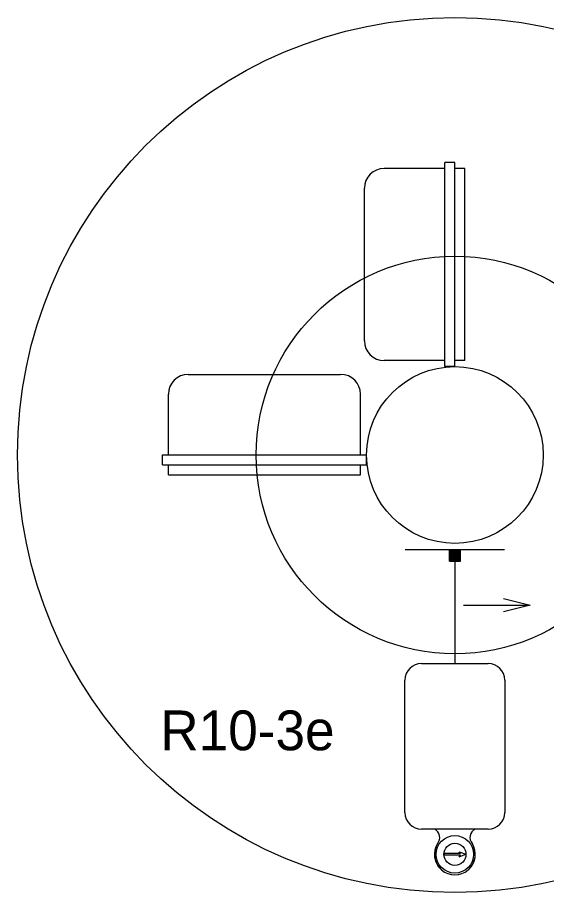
# Model space of a CAD drawing. Extents: x 1370050 to 1370716, y 380076 to 380502.
# Drawn here: x 1370528.6 to 1370568.5, y 380268.8 to 380334.9 of the extents above; entities that cross this region are included whole.
import ezdxf

# ---------------------------------------------------------------- set-up
doc = ezdxf.new("R2010")
doc.units = 0
doc.layers.add('T_Drafting', color=7, linetype='Continuous')

msp = doc.modelspace()

# ---------------------------------------------------------------- linework, layer by layer
at = {"layer": 'T_Drafting'}
for p, q in [((1370560.87, 380323.464), (1370556.287, 380323.464)), ((1370560.87, 380308.505), (1370560.87, 380323.922)), ((1370561.62, 380323.922), (1370560.87, 380323.922)), ((1370561.62, 380308.505), (1370561.62, 380323.922)), ((1370562.37, 380323.464), (1370561.62, 380323.464)), ((1370562.37, 380308.964), (1370562.37, 380323.464)), ((1370554.787, 380310.464), (1370554.787, 380321.964)), ((1370560.87, 380308.964), (1370556.287, 380308.964)), ((1370562.37, 380308.964), (1370561.62, 380308.964)), ((1370561.62, 380308.505), (1370560.87, 380308.505)), ((1370541.495, 380307.922), (1370552.995, 380307.922)), ((1370539.995, 380301.839), (1370539.995, 380306.422)), ((1370554.495, 380301.839), (1370554.495, 380306.422)), ((1370539.537, 380301.839), (1370554.953, 380301.839)), ((1370539.537, 380301.089), (1370539.537, 380301.839)), ((1370554.953, 380301.089), (1370554.953, 380301.839)), ((1370539.537, 380301.089), (1370554.953, 380301.089)), ((1370539.995, 380300.339), (1370539.995, 380301.089)), ((1370554.495, 380300.339), (1370554.495, 380301.089)), ((1370539.995, 380300.339), (1370554.495, 380300.339)), ((1370565.37, 380294.672), (1370557.87, 380294.672)), ((1370561.203, 380293.839), (1370561.203, 380294.672)), ((1370561.203, 380293.845), (1370562.031, 380294.672)), ((1370561.203, 380293.859), (1370562.017, 380294.672)), ((1370561.203, 380293.873), (1370562.002, 380294.672)), ((1370561.203, 380293.887), (1370561.988, 380294.672)), ((1370561.203, 380293.901), (1370561.974, 380294.672)), ((1370561.203, 380293.915), (1370561.96, 380294.672)), ((1370561.203, 380293.93), (1370561.946, 380294.672)), ((1370561.203, 380293.944), (1370561.932, 380294.672)), ((1370561.203, 380293.958), (1370561.918, 380294.672)), ((1370561.203, 380293.972), (1370561.903, 380294.672)), ((1370561.203, 380293.986), (1370561.889, 380294.672)), ((1370561.203, 380294), (1370561.875, 380294.672)), ((1370561.203, 380294.014), (1370561.861, 380294.672)), ((1370561.203, 380294.029), (1370561.847, 380294.672)), ((1370561.203, 380294.043), (1370561.833, 380294.672)), ((1370561.203, 380294.057), (1370561.819, 380294.672)), ((1370561.203, 380294.071), (1370561.804, 380294.672)), ((1370561.203, 380294.085), (1370561.79, 380294.672)), ((1370561.203, 380294.099), (1370561.776, 380294.672)), ((1370561.203, 380294.113), (1370561.762, 380294.672)), ((1370561.203, 380294.128), (1370561.748, 380294.672)), ((1370561.203, 380294.142), (1370561.734, 380294.672)), ((1370561.203, 380294.156), (1370561.72, 380294.672)), ((1370561.203, 380294.17), (1370561.705, 380294.672)), ((1370561.203, 380294.184), (1370561.691, 380294.672)), ((1370561.203, 380294.198), (1370561.677, 380294.672)), ((1370561.203, 380294.212), (1370561.663, 380294.672)), ((1370561.203, 380294.226), (1370561.649, 380294.672)), ((1370561.203, 380294.241), (1370561.635, 380294.672)), ((1370561.203, 380294.255), (1370561.621, 380294.672)), ((1370561.203, 380294.269), (1370561.606, 380294.672)), ((1370561.203, 380294.283), (1370561.592, 380294.672)), ((1370561.203, 380294.297), (1370561.578, 380294.672)), ((1370561.203, 380294.311), (1370561.564, 380294.672)), ((1370561.203, 380294.325), (1370561.55, 380294.672)), ((1370561.203, 380294.34), (1370561.536, 380294.672)), ((1370561.203, 380294.354), (1370561.522, 380294.672)), ((1370561.203, 380294.368), (1370561.507, 380294.672)), ((1370561.203, 380294.382), (1370561.493, 380294.672)), ((1370561.203, 380294.396), (1370561.479, 380294.672)), ((1370561.203, 380294.41), (1370561.465, 380294.672)), ((1370561.203, 380294.424), (1370561.451, 380294.672)), ((1370561.203, 380294.439), (1370561.437, 380294.672)), ((1370561.203, 380294.453), (1370561.423, 380294.672)), ((1370561.203, 380294.467), (1370561.408, 380294.672)), ((1370561.203, 380294.481), (1370561.394, 380294.672)), ((1370561.203, 380294.495), (1370561.38, 380294.672)), ((1370561.203, 380294.509), (1370561.366, 380294.672)), ((1370561.203, 380294.523), (1370561.352, 380294.672)), ((1370561.203, 380294.538), (1370561.338, 380294.672)), ((1370561.203, 380294.552), (1370561.324, 380294.672)), ((1370561.203, 380294.566), (1370561.309, 380294.672)), ((1370561.203, 380294.58), (1370561.295, 380294.672)), ((1370561.203, 380294.594), (1370561.281, 380294.672)), ((1370561.203, 380294.608), (1370561.267, 380294.672)), ((1370561.203, 380294.622), (1370561.253, 380294.672)), ((1370561.203, 380294.637), (1370561.239, 380294.672)), ((1370561.203, 380294.651), (1370561.225, 380294.672)), ((1370561.203, 380294.665), (1370561.21, 380294.672)), ((1370561.212, 380293.839), (1370562.037, 380294.664)), ((1370561.226, 380293.839), (1370562.037, 380294.65)), ((1370561.24, 380293.839), (1370562.037, 380294.636)), ((1370561.254, 380293.839), (1370562.037, 380294.621)), ((1370561.268, 380293.839), (1370562.037, 380294.607)), ((1370561.282, 380293.839), (1370562.037, 380294.593)), ((1370561.296, 380293.839), (1370562.037, 380294.579)), ((1370561.311, 380293.839), (1370562.037, 380294.565)), ((1370561.325, 380293.839), (1370562.037, 380294.551)), ((1370561.339, 380293.839), (1370562.037, 380294.537)), ((1370561.353, 380293.839), (1370562.037, 380294.522)), ((1370561.367, 380293.839), (1370562.037, 380294.508)), ((1370561.381, 380293.839), (1370562.037, 380294.494)), ((1370561.395, 380293.839), (1370562.037, 380294.48)), ((1370561.41, 380293.839), (1370562.037, 380294.466)), ((1370561.424, 380293.839), (1370562.037, 380294.452)), ((1370561.438, 380293.839), (1370562.037, 380294.438)), ((1370561.452, 380293.839), (1370562.037, 380294.423)), ((1370561.466, 380293.839), (1370562.037, 380294.409)), ((1370561.48, 380293.839), (1370562.037, 380294.395)), ((1370562.037, 380293.839), (1370562.037, 380294.672)), ((1370561.203, 380293.839), (1370562.037, 380293.839)), ((1370561.494, 380293.839), (1370562.037, 380294.381)), ((1370561.509, 380293.839), (1370562.037, 380294.367)), ((1370561.523, 380293.839), (1370562.037, 380294.353)), ((1370561.537, 380293.839), (1370562.037, 380294.339)), ((1370561.551, 380293.839), (1370562.037, 380294.324)), ((1370561.565, 380293.839), (1370562.037, 380294.31)), ((1370561.579, 380293.839), (1370562.037, 380294.296)), ((1370561.593, 380293.839), (1370562.037, 380294.282)), ((1370561.608, 380293.839), (1370562.037, 380294.268)), ((1370561.62, 380293.839), (1370561.62, 380286.103)), ((1370561.622, 380293.839), (1370562.037, 380294.254)), ((1370561.636, 380293.839), (1370562.037, 380294.24)), ((1370561.65, 380293.839), (1370562.037, 380294.225)), ((1370561.664, 380293.839), (1370562.037, 380294.211)), ((1370561.678, 380293.839), (1370562.037, 380294.197)), ((1370561.692, 380293.839), (1370562.037, 380294.183)), ((1370561.707, 380293.839), (1370562.037, 380294.169)), ((1370561.721, 380293.839), (1370562.037, 380294.155)), ((1370561.735, 380293.839), (1370562.037, 380294.141)), ((1370561.749, 380293.839), (1370562.037, 380294.126)), ((1370561.763, 380293.839), (1370562.037, 380294.112)), ((1370561.777, 380293.839), (1370562.037, 380294.098)), ((1370561.791, 380293.839), (1370562.037, 380294.084)), ((1370561.806, 380293.839), (1370562.037, 380294.07)), ((1370561.82, 380293.839), (1370562.037, 380294.056)), ((1370561.834, 380293.839), (1370562.037, 380294.042)), ((1370561.848, 380293.839), (1370562.037, 380294.027)), ((1370561.862, 380293.839), (1370562.037, 380294.013)), ((1370561.876, 380293.839), (1370562.037, 380293.999)), ((1370561.89, 380293.839), (1370562.037, 380293.985)), ((1370561.904, 380293.839), (1370562.037, 380293.971)), ((1370561.919, 380293.839), (1370562.037, 380293.957)), ((1370561.933, 380293.839), (1370562.037, 380293.943)), ((1370561.947, 380293.839), (1370562.037, 380293.928)), ((1370561.961, 380293.839), (1370562.037, 380293.914)), ((1370561.975, 380293.839), (1370562.037, 380293.9)), ((1370561.989, 380293.839), (1370562.037, 380293.886)), ((1370562.003, 380293.839), (1370562.037, 380293.872)), ((1370562.018, 380293.839), (1370562.037, 380293.858)), ((1370562.032, 380293.839), (1370562.037, 380293.844)), ((1370562.265, 380290.504), (1370567.297, 380290.504)), ((1370559.104, 380286.103), (1370564.136, 380286.103)), ((1370557.854, 380274.853), (1370557.854, 380284.853)), ((1370565.386, 380284.853), (1370565.386, 380274.853)), ((1370564.136, 380273.603), (1370559.104, 380273.603)), ((1370560.793, 380271.778), (1370560.793, 380271.628)), ((1370562.047, 380271.778), (1370560.793, 380271.778)), ((1370562.047, 380271.628), (1370560.793, 380271.628)), ((1370561.947, 380271.903), (1370562.453, 380271.703)), ((1370562.047, 380271.778), (1370561.947, 380271.903)), ((1370561.947, 380271.503), (1370562.453, 380271.703)), ((1370561.947, 380271.503), (1370562.047, 380271.628))]:
    msp.add_line(p, q, dxfattribs=at)
msp.add_lwpolyline([(1370565.297, 380291.004), (1370567.297, 380290.504), (1370565.297, 380290.004)], dxfattribs=at)
for centre, radius in [((1370561.62, 380301.839), 33.016), ((1370561.62, 380301.839), 15), ((1370561.62, 380301.839), 6.667), ((1370561.62, 380271.703), 1.417), ((1370561.62, 380271.703), 0.833)]:
    msp.add_circle(centre, radius, dxfattribs=at)
for centre, radius, start, end in [((1370556.287, 380321.964), 1.5, 90, 180), ((1370556.287, 380310.464), 1.5, 180, 270), ((1370541.495, 380306.422), 1.5, 90, 180), ((1370552.995, 380306.422), 1.5, 360, 90), ((1370559.104, 380284.853), 1.25, 90, 180), ((1370564.136, 380284.853), 1.25, 0, 90), ((1370559.104, 380274.853), 1.25, 180, 270), ((1370564.136, 380274.853), 1.25, 270, 0), ((1370559.78, 380272.969), 0.7, 318.19721, 64.80442), ((1370563.46, 380272.969), 0.7, 115.19558, 221.80279), ((1370561.62, 380271.703), 1.542, 148.74024, 227.49336), ((1370561.62, 380271.703), 1.542, 148.74024, 31.25976), ((1370561.62, 380271.703), 1.542, 312.50664, 31.25976)]:
    msp.add_arc(centre, radius, start, end, dxfattribs=at)

# ---------------------------------------------------------------- texts
msp.add_text('R10-3e', height=3, dxfattribs=at).set_placement((1370539.382, 380279.558))

doc.saveas('drawing.dxf')
